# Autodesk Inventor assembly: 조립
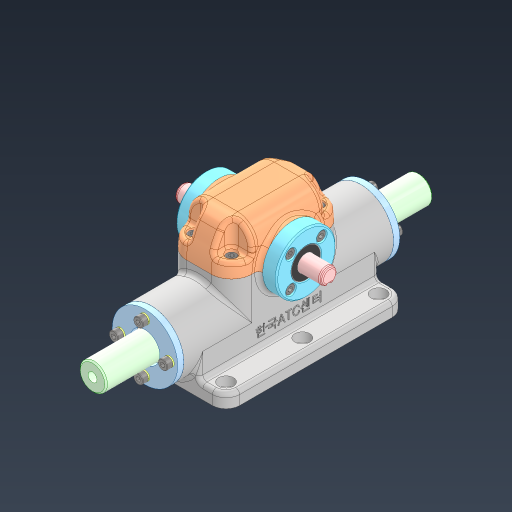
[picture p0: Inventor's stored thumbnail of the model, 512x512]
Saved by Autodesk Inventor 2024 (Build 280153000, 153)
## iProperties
Created: 2024-06
Part Number: 조립
Document SubType Name: Assembly
Designer: kh_501
Author: kh_501
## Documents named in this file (13)
- C:\Users\kh_501\Desktop\740604V1013\조립.iam
- C:\Users\kh_501\Desktop\740604V1013\본체.ipt
- C:\Users\kh_501\Desktop\740604V1013\깊은 홈 볼 베어링 6901\깊은 홈 볼 베어링 6901.ipt
- C:\Users\kh_501\Desktop\740604V1013\랙\랙.ipt
- C:\Users\kh_501\Desktop\740604V1013\베어링 커버\베어링 커버.ipt
- C:\Users\kh_501\Desktop\740604V1013\부시 커버\부시 커버.ipt
- C:\Users\kh_501\Desktop\740604V1013\스프링 와셔 M4\스프링 와셔 M4.ipt
- C:\Users\kh_501\Desktop\740604V1013\오일레스 부시\오일레스 부시.ipt
- C:\Users\kh_501\Desktop\740604V1013\오일실 12 22 7\오일실 12 22 7.ipt
- C:\Users\kh_501\Desktop\740604V1013\윗커버\윗커버.ipt
- C:\Users\kh_501\Desktop\740604V1013\육각 소켓 머리 볼트 M4x10\육각 소켓 머리 볼트 M4x10.ipt
- C:\Users\kh_501\Desktop\740604V1013\칼라\칼라.ipt
- C:\Users\kh_501\Desktop\740604V1013\피니언\피니언.ipt
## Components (1 placed, 1 different names)
1. 피니언:1 — 각도:10, 각도:11, 각도:12, 플러쉬:1
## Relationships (4: Angle 3, Flush 1)
- 각도:10 [Angle]: 피니언:1
- 각도:11 [Angle]: 피니언:1
- 각도:12 [Angle]: 피니언:1
- 플러쉬:1 [Flush]: 피니언:1
